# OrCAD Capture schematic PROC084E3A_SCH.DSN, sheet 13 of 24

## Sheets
13 09. PRG0 GB_ETHERNET RGMII 1: size C; title: PRG0 GB_ETHERNET RGMII 1
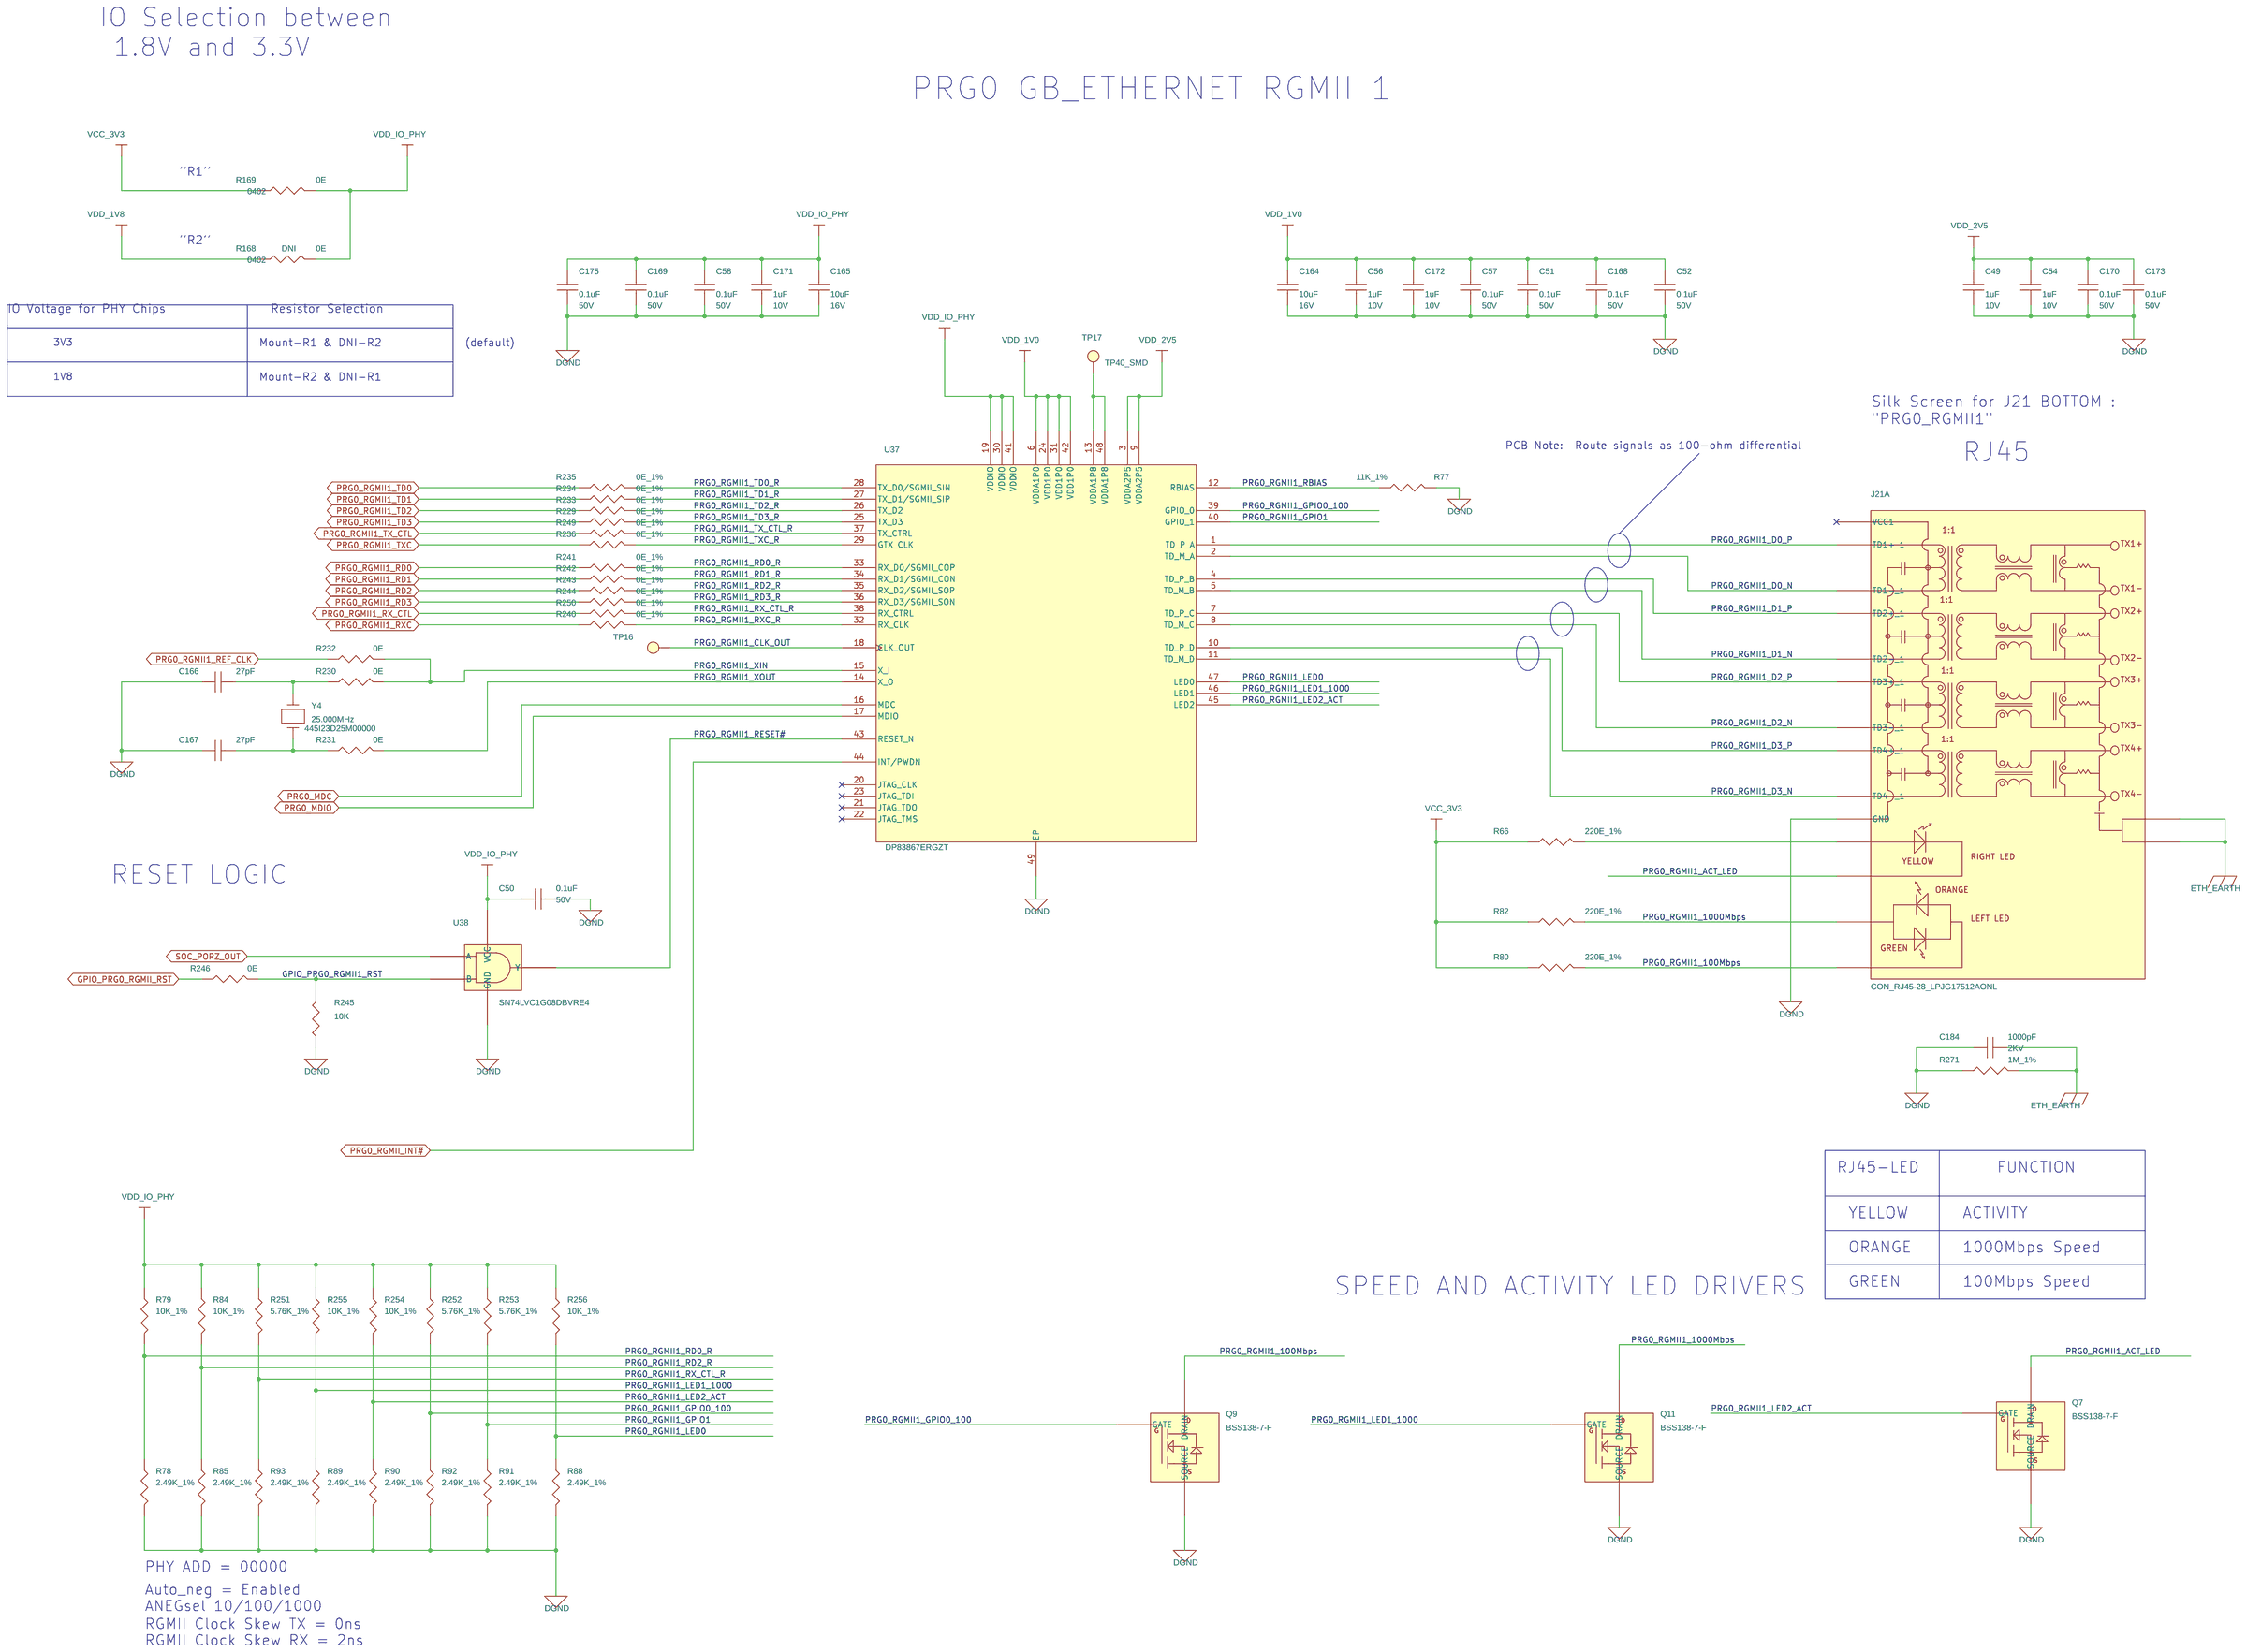
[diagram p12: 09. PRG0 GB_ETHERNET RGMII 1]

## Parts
C49  1uF  [CAP0402_0-75]
C50  0.1uF  [CAP0402_0-75]
C51  0.1uF  [CAP0402_0-75]
C52  0.1uF  [CAP0402_0-75]
C54  1uF  [CAP0402_0-75]
C56  1uF  [CAP0402_0-75]
C57  0.1uF  [CAP0402_0-75]
C58  0.1uF  [CAP0402_0-75]
C164  10uF  [CAP0805_1-5]
C165  10uF  [CAP0805_1-5]
C166  27pF  [CAP0402_0-75]
C167  27pF  [CAP0402_0-75]
C168  0.1uF  [CAP0402_0-75]
C169  0.1uF  [CAP0402_0-75]
C170  0.1uF  [CAP0402_0-75]
C171  1uF  [CAP0402_0-75]
C172  1uF  [CAP0402_0-75]
C173  0.1uF  [CAP0402_0-75]
C175  0.1uF  [CAP0402_0-75]
C184  1000pF  [CAP1206_1-75]
J21  CON_RJ45-28_LPJG17512AONL  [CON_RJ45-28_LPJG17512_S_R_T_25-3]  (sections A,B)
Q7  BSS138-7-F  [SOT23-123_1-1]
Q9  BSS138-7-F  [SOT23-123_1-1]
Q11  BSS138-7-F  [SOT23-123_1-1]
R66  220E_1%  [RES0402_0-5]
R77  11K_1%  [RES0402_0-5]
R78  2.49K_1%  [RES0402_0-5]
R79  10K_1%  [RES0402_0-5]
R80  220E_1%  [RES0402_0-5]
R82  220E_1%  [RES0402_0-5]
R84  10K_1%  [RES0402_0-5]
R85  2.49K_1%  [RES0402_0-5]
R88  2.49K_1%  [RES0402_0-5]
R89  2.49K_1%  [RES0402_0-5]
R90  2.49K_1%  [RES0402_0-5]
R91  2.49K_1%  [RES0402_0-5]
R92  2.49K_1%  [RES0402_0-5]
R93  2.49K_1%  [RES0402_0-5]
R168  0E  [RES0402_0-5]
R169  0E  [RES0402_0-5]
R229  0E_1%  [RES0402_0-5]
R230  0E  [RES0402_0-5]
R231  0E  [RES0402_0-5]
R232  0E  [RES0402_0-5]
R233  0E_1%  [RES0402_0-5]
R234  0E_1%  [RES0402_0-5]
R235  0E_1%  [RES0402_0-5]
R236  0E_1%  [RES0402_0-5]
R240  0E_1%  [RES0402_0-5]
R241  0E_1%  [RES0402_0-5]
R242  0E_1%  [RES0402_0-5]
R243  0E_1%  [RES0402_0-5]
R244  0E_1%  [RES0402_0-5]
R245  10K  [RES0402_0-5]
R246  0E  [RES0402_0-5]
R249  0E_1%  [RES0402_0-5]
R250  0E_1%  [RES0402_0-5]
R251  5.76K_1%  [RES0402_0-5]
R252  5.76K_1%  [RES0402_0-5]
R253  5.76K_1%  [RES0402_0-5]
R254  10K_1%  [RES0402_0-5]
R255  10K_1%  [RES0402_0-5]
R256  10K_1%  [RES0402_0-5]
R271  1M_1%  [RES0805_0-75]
TP16  TP40_SMD  [TP40_SMD]
TP17  TP40_SMD  [TP40_SMD]
U37  DP83867ERGZT  [VQFN48_19-68_285X285]
U38  SN74LVC1G08DBVRE4  [SOT23-5]
Y4  25.000MHz  [XTAL_ABM3_205X130_SMD_1-4]

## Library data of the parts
C49 C54 C56 C171 C172 = CAP: CAP CERAMIC 1uF 10V 10% X5R 0402; Chkd/date: MANIRAJA/020718; Crtd /date: SARANYA/060514; Custom_Duty: 15%; Customs_HS_Code: 85322990; Distributor_name: DIGIKEY; Distributor_part_number: 478-4596-1-ND; Footprint Path: Y:\MIS_DATABASE\Library\ALTIUM_TOOL\PCB_FOOTPRINTS\Altium_Footprint_Lib.PcbLib; Height: 0.56MM; Library Path: Y:\MIS_DATABASE\Library\ALTIUM_TOOL\SCHEMATICS_PARTS\MS_DISCRETE_Library.schlib; Mfr_name: AVX CORPORATION; Mfr_part_number: 0402ZD105KAT2A; Mistral Part No: 120014050010-R; Package: 0402; Part_type: CAPACITORS\CERAMIC; Project: AEGIS GP BETA2; RoHS: RoHS; Temperature: -55°C+85°C; Tolerance: 10%; Voltage: 10V; Wattage: NA; Weight: 0.65mg; Datasheet: Y:\MIS_DATABASE\DATASHEETS\CAPACITORS\AVX_MLC.PDF
C50-C52 C57 C58 C168-C170 C173 C175 = CAP: CAP CERAMIC 0.1uF 50V 10% X7R 0402; Chkd/date: VASANTHA/281216; Crtd /date: CHAITHANYA/051011; Custom_Duty: 15%; Customs_HS_Code: 85322990; Distributor_name: DIGIKEY; Distributor_part_number: 445-173610-1-ND; Footprint Path: Y:\MIS_DATABASE\Library\ALTIUM_TOOL\PCB_FOOTPRINTS\Altium_Footprint_Lib.PcbLib; Height: 0.60MM; Library Path: Y:\MIS_DATABASE\Library\ALTIUM_TOOL\SCHEMATICS_PARTS\MS_DISCRETE_Library.schlib; Mfr_name: TDK CORPORATION; Mfr_part_number: C1005X7R1H104K050BE; Mistral Part No: 120011100014-R; Package: 0402; Part_type: CAPACITORS\CERAMIC; Project: VP-4000-BASE-BOARD; RoHS: RoHS; Temperature: -55°C+125°C; Tolerance: 10%; Voltage: 50V; Wattage: NA; Weight: 0.65mg; Datasheet: Y:\MIS_DATABASE\DATASHEETS\CAPACITORS\TDK_C-SER_FEB19.PDF
C164 C165 = CAP: CAP CERAMIC 10uF 16V 10% X5R 0805; Chkd/date: SHREESHAIL/220506; Crtd /date: MAZHAR/150506; Custom_Duty: 15%; Customs_HS_Code: 85322990; Distributor_name: DIGIKEY; Distributor_part_number: 490-3886-1-ND; Footprint Path: Y:\MIS_DATABASE\Library\ALTIUM_TOOL\PCB_FOOTPRINTS\Altium_Footprint_Lib.PcbLib; Height: 1.35MM; Library Path: Y:\MIS_DATABASE\Library\ALTIUM_TOOL\SCHEMATICS_PARTS\MS_DISCRETE_Library.schlib; Mfr_name: MURATA; Mfr_part_number: GRM21BR61C106KE15L; Mistral Part No: 120009030205-R; Package: 0805; Part_type: CAPACITORS\CERAMIC; Project: VOCERA; RoHS: RoHS; Temperature: -55°C+85°C; Tolerance: 10%; Voltage: 16V; Wattage: NA; Weight: 9.5mg; Datasheet: Y:\MIS_DATABASE\DATASHEETS\CAPACITORS\MURATA-GXX-SER_NOV17.PDF
C166 = CAP: CAP CERAMIC 27pF 50V 5% C0G(NP0) 0402; Chkd/date: MAZHAR/241208; Crtd /date: GEETHA/090606; Custom_Duty: 15%; Customs_HS_Code: 85322990; Distributor_name: DIGIKEY; Distributor_part_number: 311-1019-1-ND; Footprint Path: Y:\MIS_DATABASE\Library\ALTIUM_TOOL\PCB_FOOTPRINTS\Altium_Footprint_Lib.PcbLib; Height: 0.55MM; Library Path: Y:\MIS_DATABASE\Library\ALTIUM_TOOL\SCHEMATICS_PARTS\MS_DISCRETE_Library.schlib; Mfr_name: YAGEO AMERICA; Mfr_part_number: CC0402JRNPO9BN270; Mistral Part No: 120014100024-R; Package: 0402; Part_type: CAPACITORS\CERAMIC; Project: PNAV; RoHS: RoHS; Temperature: -55°C+125°C; Tolerance: 5%; Voltage: 50V; Wattage: NA; Weight: 0.65mg; Datasheet: Y:\MIS_DATABASE\DATASHEETS\CAPACITORS\YACC-NPO.PDF
C167 = CAP: CAP CERAMIC 27pF 50V 5% C0G(NP0) 0402; Chkd/date: MAZHAR/241208; Crtd /date: GEETHA/090606; Custom_Duty: 15%; Customs_HS_Code: 85322990; Distributor_name: DIGIKEY; Distributor_part_number: 311-1019-1-ND; Footprint Path: Y:\MIS_DATABASE\Library\ALTIUM_TOOL\PCB_FOOTPRINTS\Altium_Footprint_Lib.PcbLib; Height: 0.55MM; Library Path: Y:\MIS_DATABASE\Library\ALTIUM_TOOL\SCHEMATICS_PARTS\MS_DISCRETE_Library.schlib; Mfr_name: YAGEO AMERICA; Mfr_part_number: CC0402JRNPO9BN270; Mistral Part No: 120014100024-R; Package: 0402; Part_type: CAPACITORS\CERAMIC; Project: PNAV; RoHS: RoHS; SIGNAL_MODEL: INS23888586; Temperature: -55°C+125°C; Tolerance: 5%; Voltage: 50V; Wattage: NA; Weight: 0.65mg; Datasheet: Y:\MIS_DATABASE\DATASHEETS\CAPACITORS\YACC-NPO.PDF
C184 = CAP: CAP CERAMIC 1000pF 2KV 10% X7R 1206; Chkd/date: SHREESHAIL/291106; Crtd /date: MAZHAR/281106; Custom_Duty: 15%; Customs_HS_Code: 85322990; Distributor_name: DIGIKEY; Distributor_part_number: 478-2956-1-ND; Footprint Path: Y:\MIS_DATABASE\Library\ALTIUM_TOOL\PCB_FOOTPRINTS\Altium_Footprint_Lib.PcbLib; Height: 1.52MM; Library Path: Y:\MIS_DATABASE\Library\ALTIUM_TOOL\SCHEMATICS_PARTS\MS_DISCRETE_Library.schlib; Mfr_name: AVX CORPORATION; Mfr_part_number: 1206GC102KAT1A; Mistral Part No: 120015080006-R; Package: 1206; Part_type: CAPACITORS\CERAMIC; Project: ADR1B; RoHS: RoHS; Temperature: -55°C+125°C; Tolerance: 10%; Voltage: 2KV; Wattage: NA; Weight: 16.2mg; Datasheet: Y:\MIS_DATABASE\DATASHEETS\CAPACITORS\AVX_HV-MLC.PDF
J21 = CON_RJ45-28_LPJG17512AONL: CON JACK RJ45 28POS REGISTERED FEMALE RA TH; Chkd/date: MANIRAJA/010817; Crtd /date: MANIRAJA/010817; Custom_Duty: 24%; Customs_HS_Code: 85369090; Distributor_name: NA; Distributor_part_number: NA; Height: 25.30MM; Mfr_name: LINK-PP; Mfr_part_number: LPJG17512AONL; Mistral Part No: 150017080001-R; Package: THRU-HOLE; Part_type: CONNECTOR\JACK; Project: TI_SVB_DUT; RoHS: RoHS; Temperature: 0°C+70°C; Tolerance: NA; Voltage: NA; Wattage: NA; Weight: NA; Datasheet: Y:\MIS_DATABASE\DATASHEETS\CONNECTORS\LPJG17512AONL.PDF
Q7 Q9 Q11 = MOSFET_2N7002_SOT23: IC MOSFET N-CHANNEL 50V 200mA SOT23-123; Chkd/date: MANIRAJA/190618; Crtd /date: USMAN/240709; Custom_Duty: 15%; Customs_HS_Code: 85423100; Distributor_name: DIGIKEY; Distributor_part_number: BSS138-FDICT-ND; Footprint Path: Y:\MIS_DATABASE\Library\ALTIUM_TOOL\PCB_FOOTPRINTS\Altium_Footprint_Lib.PcbLib; Height: 1.10MM; Library Path: Y:\MIS_DATABASE\Library\ALTIUM_TOOL\SCHEMATICS_PARTS\MS_MOSFET_Library.schlib; Mfr_name: DIODES INC; Mistral Part No: 142009070019-R; Package: SOT23-123; Part_type: ICS\POWER\MOSFET; Project: KHAN_MAIN; RoHS: RoHS; Temperature: -55°C+150°C; Tolerance: NA; Voltage: 50V; Wattage: 300mW; Weight: 8mg; Datasheet: Y:\MIS_DATABASE\DATASHEETS\DISCRETES\TRANSISTORS_FETS\BSS138.PDF
R66 R80 R82 = RESISTOR: RES 220E 1/10W 1% 0402; Chkd/date: MANIRAJA/130617; Crtd /date: BAVISH/260711; Custom_Duty: 15%; Customs_HS_Code: 85332119; Distributor_name: DIGIKEY; Distributor_part_number: P220LCT-ND; Footprint Path: Y:\MIS_DATABASE\Library\ALTIUM_TOOL\PCB_FOOTPRINTS\Altium_Footprint_Lib.PcbLib; Height: 0.40MM; Library Path: Y:\MIS_DATABASE\Library\ALTIUM_TOOL\SCHEMATICS_PARTS\MS_DISCRETE_Library.schlib; Mfr_name: PANASONIC-ECG; Mfr_part_number: ERJ-2RKF2200X; Mistral Part No: 110011070017-R; Package: 0402; Part_type: RESISTORS\FIXED; Project: LSM; RoHS: RoHS; Temperature: -55°C+155°C; Tolerance: 1%; Voltage: NA; Wattage: 1/10W; Weight: 0.8mg; Datasheet: Y:\MIS_DATABASE\DATASHEETS\RESISTORS\PAN-ERJSER_NOV17.PDF
R77 = RESISTOR: RES 11K 1/16W 1% 0402; Chkd/date: VASANTHA/251115; Crtd /date: VASANTHA/251115; Custom_Duty: 15%; Customs_HS_Code: 85332119; Distributor_name: DIGIKEY; Distributor_part_number: 311-11.0KLRCT-ND; Footprint Path: Y:\MIS_DATABASE\Library\ALTIUM_TOOL\PCB_FOOTPRINTS\Altium_Footprint_Lib.PcbLib; Height: 0.40MM; Library Path: Y:\MIS_DATABASE\Library\ALTIUM_TOOL\SCHEMATICS_PARTS\MS_DISCRETE_Library.schlib; Mfr_name: YAGEO AMERICA; Mfr_part_number: RC0402FR-0711KL; Mistral Part No: 110015110012-R; Package: 0402; Part_type: RESISTORS\FIXED; Project: TI_VLAN_SWITCH; RoHS: RoHS; Temperature: -55°C+155°C; Tolerance: 1%; Voltage: NA; Wattage: 1/16W; Weight: 0.65mg; Datasheet: Y:\MIS_DATABASE\DATASHEETS\RESISTORS\RCXXXXL-SER_MAR18.PDF
R78 R85 R88 R90-R92 = RESISTOR: RES 2.49K 1/16W 1% 0402; Assembly_Instruction: DNI; Chkd/date: VASANTHA/270516; Crtd /date: VASANTHA/270516; Custom_Duty: 15%; Customs_HS_Code: 85332119; Distributor_name: DIGIKEY; Distributor_part_number: 311-2.49KLRCT-ND; Footprint Path: Y:\MIS_DATABASE\Library\ALTIUM_TOOL\PCB_FOOTPRINTS\Altium_Footprint_Lib.PcbLib; Height: 0.40MM; Library Path: Y:\MIS_DATABASE\Library\ALTIUM_TOOL\SCHEMATICS_PARTS\MS_DISCRETE_Library.schlib; Mfr_name: YAGEO AMERICA; Mfr_part_number: RC0402FR-072K49L; Mistral Part No: 110016050020-R; Package: 0402; Part_type: RESISTORS\FIXED; Project: TMDXCSKCC; RoHS: RoHS; Temperature: -55°C+155°C; Tolerance: 1%; Voltage: NA; Wattage: 1/16W; Weight: 0.65mg; Datasheet: Y:\MIS_DATABASE\DATASHEETS\RESISTORS\RCXXXXL-SER_MAR18.PDF
R79 R84 R254 R256 = RESISTOR: RES 10K 1/16W 1% 0402; Assembly_Instruction: DNI; Chkd/date: VASANTHA/201216; Crtd /date: GEETHA/290506; Custom_Duty: 15%; Customs_HS_Code: 85332119; Distributor_name: DIGIKEY; Distributor_part_number: 311-10.0KLRTR-ND; Footprint Path: Y:\MIS_DATABASE\Library\ALTIUM_TOOL\PCB_FOOTPRINTS\Altium_Footprint_Lib.PcbLib; Height: 0.40MM; Library Path: Y:\MIS_DATABASE\Library\ALTIUM_TOOL\SCHEMATICS_PARTS\MS_DISCRETE_Library.schlib; Mfr_name: YAGEO AMERICA; Mfr_part_number: RC0402FR-0710KL; Mistral Part No: 110015090015-R; Package: 0402; Part_type: RESISTORS\FIXED; Project: VOCERA; RoHS: RoHS; Temperature: -55°C+155°C; Tolerance: 1%; Voltage: NA; Wattage: 1/16W; Weight: 0.65mg; Datasheet: Y:\MIS_DATABASE\DATASHEETS\RESISTORS\RCXXXXL-SER_MAR18.PDF
R89 R93 = RESISTOR: RES 2.49K 1/16W 1% 0402; Chkd/date: VASANTHA/270516; Crtd /date: VASANTHA/270516; Custom_Duty: 15%; Customs_HS_Code: 85332119; Distributor_name: DIGIKEY; Distributor_part_number: 311-2.49KLRCT-ND; Footprint Path: Y:\MIS_DATABASE\Library\ALTIUM_TOOL\PCB_FOOTPRINTS\Altium_Footprint_Lib.PcbLib; Height: 0.40MM; Library Path: Y:\MIS_DATABASE\Library\ALTIUM_TOOL\SCHEMATICS_PARTS\MS_DISCRETE_Library.schlib; Mfr_name: YAGEO AMERICA; Mfr_part_number: RC0402FR-072K49L; Mistral Part No: 110016050020-R; Package: 0402; Part_type: RESISTORS\FIXED; Project: TMDXCSKCC; RoHS: RoHS; Temperature: -55°C+155°C; Tolerance: 1%; Voltage: NA; Wattage: 1/16W; Weight: 0.65mg; Datasheet: Y:\MIS_DATABASE\DATASHEETS\RESISTORS\RCXXXXL-SER_MAR18.PDF
R168 = RESISTOR: RES 0E 1/10W JUMPER 0402; Assembly_Instruction: DNI; Chkd/date: VASANTHA/061216; Crtd /date: NAVEED/201014; Custom_Duty: 15%; Customs_HS_Code: 85332119; Distributor_name: DIGIKEY; Distributor_part_number: P0.0JCT-ND; Footprint Path: Y:\MIS_DATABASE\Library\ALTIUM_TOOL\PCB_FOOTPRINTS\Altium_Footprint_Lib.PcbLib; Height: 0.40MM; IBISSP_MODLES: VALUE REPEATING 2 TIME; Library Path: Y:\MIS_DATABASE\Library\ALTIUM_TOOL\SCHEMATICS_PARTS\MS_DISCRETE_Library.schlib; Mfr_name: PANASONIC-ECG; Mfr_part_number: ERJ-2GE0R00X; Mistral Part No: 110018030052-R; Package: 0402; Part_type: RESISTORS\FIXED; Project: AEGIS POM; RoHS: RoHS; SIGNAL_MODEL: INS23888567; Temperature: -55°C+155°C; Tolerance: NA; Voltage: NA; Wattage: 1/10W; Weight: 0.8mg; Datasheet: Y:\MIS_DATABASE\DATASHEETS\RESISTORS\PAN-ERJSER_NOV17.PDF
R169 = RESISTOR: RES 0E 1/10W JUMPER 0402; Chkd/date: VASANTHA/061216; Crtd /date: NAVEED/201014; Custom_Duty: 15%; Customs_HS_Code: 85332119; Distributor_name: DIGIKEY; Distributor_part_number: P0.0JCT-ND; Footprint Path: Y:\MIS_DATABASE\Library\ALTIUM_TOOL\PCB_FOOTPRINTS\Altium_Footprint_Lib.PcbLib; Height: 0.40MM; IBISSP_MODLES: VALUE REPEATING 2 TIME; Library Path: Y:\MIS_DATABASE\Library\ALTIUM_TOOL\SCHEMATICS_PARTS\MS_DISCRETE_Library.schlib; Mfr_name: PANASONIC-ECG; Mfr_part_number: ERJ-2GE0R00X; Mistral Part No: 110018030052-R; Package: 0402; Part_type: RESISTORS\FIXED; Project: AEGIS POM; RoHS: RoHS; SIGNAL_MODEL: INS23888567; Temperature: -55°C+155°C; Tolerance: NA; Voltage: NA; Wattage: 1/10W; Weight: 0.8mg; Datasheet: Y:\MIS_DATABASE\DATASHEETS\RESISTORS\PAN-ERJSER_NOV17.PDF
R229 R233-R236 R249 = RESISTOR: RES 0E 1/16W 1% 0402; Chkd/date: MAZHAR/220709; Crtd /date: USMAN/270109; Custom_Duty: 15%; Customs_HS_Code: 85332119; Distributor_name: DIGIKEY; Distributor_part_number: 311-0.0LRCT-ND; Footprint Path: Y:\MIS_DATABASE\Library\ALTIUM_TOOL\PCB_FOOTPRINTS\Altium_Footprint_Lib.PcbLib; Height: 0.40MM; Library Path: Y:\MIS_DATABASE\Library\ALTIUM_TOOL\SCHEMATICS_PARTS\MS_DISCRETE_Library.schlib; Mfr_name: YAGEO AMERICA; Mfr_part_number: RC0402FR-070RL; Mistral Part No: 110009030085-R; Package: 0402; Part_type: RESISTORS\FIXED; Project: OMAP_EVM; RoHS: RoHS; SIGNAL_MODEL: INS23888567; Temperature: -55°C+155°C; Tolerance: 1%; Voltage: NA; Wattage: 1/16W; Weight: 0.65mg; Datasheet: Y:\MIS_DATABASE\DATASHEETS\RESISTORS\RCXXXXL-SER_MAR18.PDF
R230 R231 R246 = RESISTOR: RES 0E 1/10W JUMPER 0402; Chkd/date: MANIRAJA/290318; Crtd /date: ALVY/270318; Custom_Duty: 15%; Customs_HS_Code: 85332119; Distributor_name: DIGIKEY; Distributor_part_number: MCS0402-0.0-ZZCT-ND; Footprint Path: Y:\MIS_DATABASE\Library\ALTIUM_TOOL\PCB_FOOTPRINTS\Altium_Footprint_Lib.PcbLib; Height: 0.37MM; Library Path: Y:\MIS_DATABASE\Library\ALTIUM_TOOL\SCHEMATICS_PARTS\MS_DISCRETE_Library.schlib; Mfr_name: VISHAY; Mfr_part_number: MCS04020Z0000ZE000; Mistral Part No: 110018030052-R; Package: 0402; Part_type: RESISTORS\FIXED; Project: DRDL_ITS2-SC; RoHS: RoHS; SIGNAL_MODEL: INS23888567; Temperature: -55°C+155°C; Tolerance: NA; Voltage: NA; Wattage: 1/10W; Weight: 0.65mg; Datasheet: Y:\MIS_DATABASE\DATASHEETS\RESISTORS\MCTXXXXC-SER.PDF
R232 = RESISTOR: RES 0E 1/10W JUMPER 0402; Assembly_Instruction: DNI; Chkd/date: MANIRAJA/290318; Crtd /date: ALVY/270318; Custom_Duty: 15%; Customs_HS_Code: 85332119; Distributor_name: DIGIKEY; Distributor_part_number: MCS0402-0.0-ZZCT-ND; Footprint Path: Y:\MIS_DATABASE\Library\ALTIUM_TOOL\PCB_FOOTPRINTS\Altium_Footprint_Lib.PcbLib; Height: 0.37MM; Library Path: Y:\MIS_DATABASE\Library\ALTIUM_TOOL\SCHEMATICS_PARTS\MS_DISCRETE_Library.schlib; Mfr_name: VISHAY; Mfr_part_number: MCS04020Z0000ZE000; Mistral Part No: 110018030052-R; Package: 0402; Part_type: RESISTORS\FIXED; Project: DRDL_ITS2-SC; RoHS: RoHS; SIGNAL_MODEL: INS23888567; Temperature: -55°C+155°C; Tolerance: NA; Voltage: NA; Wattage: 1/10W; Weight: 0.65mg; Datasheet: Y:\MIS_DATABASE\DATASHEETS\RESISTORS\MCTXXXXC-SER.PDF
R240-R244 R250 = RESISTOR: RES 0E 1/16W 1% 0402; Chkd/date: MAZHAR/220709; Crtd /date: USMAN/270109; Custom_Duty: 15%; Customs_HS_Code: 85332119; Distributor_name: DIGIKEY; Distributor_part_number: 311-0.0LRCT-ND; Footprint Path: Y:\MIS_DATABASE\Library\ALTIUM_TOOL\PCB_FOOTPRINTS\Altium_Footprint_Lib.PcbLib; Height: 0.40MM; Library Path: Y:\MIS_DATABASE\Library\ALTIUM_TOOL\SCHEMATICS_PARTS\MS_DISCRETE_Library.schlib; Mfr_name: YAGEO AMERICA; Mfr_part_number: RC0402FR-070RL; Mistral Part No: 110009030085-R; Package: 0402; Part_type: RESISTORS\FIXED; Project: OMAP_EVM; RoHS: RoHS; SIGNAL_MODEL: RESISTOR_RES0402_22E_1%_22E_1%; Temperature: -55°C+155°C; Tolerance: 1%; Voltage: NA; Wattage: 1/16W; Weight: 0.65mg; Datasheet: Y:\MIS_DATABASE\DATASHEETS\RESISTORS\RCXXXXL-SER_MAR18.PDF
R245 = RESISTOR: RES 10K 1/16W 5% 0402; Chkd/date: VASANTHA/061216; Crtd /date: MAZHAR/230805; Custom_Duty: 15%; Customs_HS_Code: 85332119; Distributor_name: DIGIKEY; Distributor_part_number: 311-10KJRCT-ND; Footprint Path: Y:\MIS_DATABASE\Library\ALTIUM_TOOL\PCB_FOOTPRINTS\Altium_Footprint_Lib.PcbLib; Height: 0.40MM; Library Path: Y:\MIS_DATABASE\Library\ALTIUM_TOOL\SCHEMATICS_PARTS\MS_DISCRETE_Library.schlib; Loading: DNI; Mfr_name: YAGEO AMERICA; Mfr_part_number: RC0402JR-0710KL; Mistral Part No: 110011060021-R; Package: 0402; Part_type: RESISTORS\FIXED; Project: HSE; RoHS: RoHS; Temperature: -55°C+155°C; Tolerance: 5%; Voltage: NA; Wattage: 1/16W; Weight: 0.65mg; Datasheet: Y:\MIS_DATABASE\DATASHEETS\RESISTORS\RCXXXXL-SER_MAR18.PDF
R251 = RESISTOR: RES 5.76K 1/10W 1% 0402; Chkd/date: MAZHAR/150709; Crtd /date: USMAN/220808; Custom_Duty: 15%; Customs_HS_Code: 85332119; Distributor_name: DIGIKEY; Distributor_part_number: P5.76KLCT-ND; Footprint Path: Y:\MIS_DATABASE\Library\ALTIUM_TOOL\PCB_FOOTPRINTS\Altium_Footprint_Lib.PcbLib; Height: 0.40MM; Library Path: Y:\MIS_DATABASE\Library\ALTIUM_TOOL\SCHEMATICS_PARTS\MS_DISCRETE_Library.schlib; Mfr_name: PANASONIC-ECG; Mfr_part_number: ERJ-2RKF5761X; Mistral Part No: 110009030945-R; Package: 0402; Part_type: RESISTORS\FIXED; Project: CPB; RoHS: RoHS; Temperature: -55°C+155°C; Tolerance: 1%; Voltage: NA; Wattage: 1/10W; Weight: 0.8mg; Datasheet: Y:\MIS_DATABASE\DATASHEETS\RESISTORS\PAN-ERJSER_NOV17.PDF
R252 R253 = RESISTOR: RES 5.76K 1/10W 1% 0402; Assembly_Instruction: DNI; Chkd/date: MAZHAR/150709; Crtd /date: USMAN/220808; Custom_Duty: 15%; Customs_HS_Code: 85332119; Distributor_name: DIGIKEY; Distributor_part_number: P5.76KLCT-ND; Footprint Path: Y:\MIS_DATABASE\Library\ALTIUM_TOOL\PCB_FOOTPRINTS\Altium_Footprint_Lib.PcbLib; Height: 0.40MM; Library Path: Y:\MIS_DATABASE\Library\ALTIUM_TOOL\SCHEMATICS_PARTS\MS_DISCRETE_Library.schlib; Mfr_name: PANASONIC-ECG; Mfr_part_number: ERJ-2RKF5761X; Mistral Part No: 110009030945-R; Package: 0402; Part_type: RESISTORS\FIXED; Project: CPB; RoHS: RoHS; Temperature: -55°C+155°C; Tolerance: 1%; Voltage: NA; Wattage: 1/10W; Weight: 0.8mg; Datasheet: Y:\MIS_DATABASE\DATASHEETS\RESISTORS\PAN-ERJSER_NOV17.PDF
R255 = RESISTOR: RES 10K 1/16W 1% 0402; Chkd/date: VASANTHA/201216; Crtd /date: GEETHA/290506; Custom_Duty: 15%; Customs_HS_Code: 85332119; Distributor_name: DIGIKEY; Distributor_part_number: 311-10.0KLRTR-ND; Footprint Path: Y:\MIS_DATABASE\Library\ALTIUM_TOOL\PCB_FOOTPRINTS\Altium_Footprint_Lib.PcbLib; Height: 0.40MM; Library Path: Y:\MIS_DATABASE\Library\ALTIUM_TOOL\SCHEMATICS_PARTS\MS_DISCRETE_Library.schlib; Mfr_name: YAGEO AMERICA; Mfr_part_number: RC0402FR-0710KL; Mistral Part No: 110015090015-R; Package: 0402; Part_type: RESISTORS\FIXED; Project: VOCERA; RoHS: RoHS; Temperature: -55°C+155°C; Tolerance: 1%; Voltage: NA; Wattage: 1/16W; Weight: 0.65mg; Datasheet: Y:\MIS_DATABASE\DATASHEETS\RESISTORS\RCXXXXL-SER_MAR18.PDF
R271 = RESISTOR: RES 1M 1/8W 1% 0805; Chkd/date: VASANTHA/150514; Crtd /date: BALACHANDAR/150514; Custom_Duty: 15%; Customs_HS_Code: 85332119; Distributor_name: DIGIKEY; Distributor_part_number: P1.00MCCT-ND; Footprint Path: Y:\MIS_DATABASE\Library\ALTIUM_TOOL\PCB_FOOTPRINTS\Altium_Footprint_Lib.PcbLib; Height: 0.70MM; Library Path: Y:\MIS_DATABASE\Library\ALTIUM_TOOL\SCHEMATICS_PARTS\MS_DISCRETE_Library.schlib; Mfr_name: PANASONIC-ECG; Mfr_part_number: ERJ-6ENF1004V; Mistral Part No: 110014100002-R; Package: 0805; Part_type: RESISTORS\FIXED; Project: HUMANWARE_PHOENIX; RoHS: RoHS; Temperature: -55°C+155°C; Tolerance: 1%; Voltage: NA; Wattage: 1/8W; Weight: 4mg; Datasheet: Y:\MIS_DATABASE\DATASHEETS\RESISTORS\PAN-ERJSER_NOV17.PDF
TP16 TP17 = TESTPOINT: TESTPOINT CIR 40 SMD; Chkd/date: MAZHAR/190505; Crtd /date: MAZHAR/190505; Distributor_name: NA; Distributor_part_number: NA; Footprint Path: Y:\MIS_DATABASE\Library\ALTIUM_TOOL\PCB_FOOTPRINTS\Altium_Footprint_Lib.PcbLib; Height: NA; Library Path: Y:\MIS_DATABASE\Library\ALTIUM_TOOL\SCHEMATICS_PARTS\MS_DISCRETE_Library.schlib; MECHANICAL 3D STEP FILE: NA; Mfr_name: LOCAL; Mistral Part No: 130009030933; Package: SMD; Project: RAINIER-3; RoHS: NA; Temperature: NA; Tolerance: NA; Voltage: NA; Wattage: NA; Weight: NA; Datasheet: NA
U37 = DP83867ERGZT_VQFN48: IC SMALL FORM FACTOR 10/100/1000 Mb/s ETHERNET PHY LAYER TRANSCEIVER VQFN48; Chkd/date: VASANTHA/251115; Crtd /date: VASANTHA/251115; Custom_Duty: 15%; Customs_HS_Code: 85423100; Distributor_name: DIGIKEY; Distributor_part_number: 296-43254-1-ND; Height: 1.00MM; Mfr_name: TEXAS INSTRUMENTS; Mistral Part No: 143015110004-R; Package: VQFN48; Part_type: ICS\TELECOM\TRANSCEIVER; Project: TI_VLAN_SWITCH; RoHS: RoHS; Temperature: -40°C+105°C; Tolerance: NA; Voltage: NA; Wattage: NA; Weight: NA; Datasheet: Y:\MIS_DATABASE\DATASHEETS\ICS\DIGITAL\BUSTRANSCEIVER\DP83867.PDF
U38 = SN74LVC1G08DBVRE4_SOT23-5: IC SINGLE 2-INPUT POSITIVE AND GATE SOT23-5; Chkd/date: SUHAS/221010; Crtd /date: USMAN/151008; Custom_Duty: 15%; Customs_HS_Code: 85423100; Distributor_name: DIGIKEY; Distributor_part_number: SN74LVC1G08DBVRE4-ND; Height: 1.45MM; Mfr_name: TEXAS INSTRUMENTS; Mistral Part No: 141009060026-R; Part_type: ICS\DIGITAL\GATES; Project: KHAN_MAIN; RoHS: Sb/ Br FREE; Temperature: -40°C+85°C; Datasheet: Y:\MIS_DATABASE\DATASHEETS\ICS\DIGITAL\GATES\SN74LVC1G08.PDF
Y4 = CRY: CRY 25.000MHz 18pF SMD; Chkd/date: VASANTHA/110316; Crtd /date: JEBRAN/090216; Custom_Duty: 24%; Customs_HS_Code: 85439000; Distributor_name: DIGIKEY; Distributor_part_number: CTX1175CT-ND; Footprint Path: Y:\MIS_DATABASE\Library\ALTIUM_TOOL\PCB_FOOTPRINTS\Altium_Footprint_Lib.PcbLib; Height: 1.35MM; Library Path: Y:\MIS_DATABASE\Library\ALTIUM_TOOL\SCHEMATICS_PARTS\MS_DISCRETE_Library.schlib; Mfr_name: CTS; Mfr_part_number: 445I23D25M00000; Mistral Part No: 130016020016-R; Package: SMD; Part_type: CRYSTAL; Project: PDI_MINIPCB; RoHS: RoHS; Temperature: -40°C+85°C; Tolerance: NA; Voltage: NA; Wattage: NA; Weight: 50mg; Datasheet: Y:\MIS_DATABASE\DATASHEETS\MISC\CRY_OSC\445.PDF

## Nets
DGND: C49.2 C50.2 C51.2 C52.2 C54.2 C56.2 C57.2 C58.2 C164.2 C165.2 C166.1 C167.1 C168.2 C169.2 C170.2 C171.2 C172.2 C173.2 C175.2 C184.1 J21.A10(GND) Q7.2(SOURCE) Q9.2(SOURCE) Q11.2(SOURCE) R77.1 R78.2 R85.2 R88.2 R89.2 R90.2 R91.2 R92.2 R93.2 R245.1 R271.1 U37.49(EP) U38.3(GND) ; also on sheet 1 2 3 8 9 10 11 12 14 15 16 17 18 19 20 21 22 23 24
VCC_3V3: R66.1 R80.1 R82.1 R169.2 ; also on sheet 1 2 3 8 9 10 11 12 14 15 16 17 18 19 20 22 23 24
VDD_1V0: C51.1 C52.1 C56.1 C57.1 C164.1 C168.1 C172.1 U37.6(VDDA1P0) U37.24(VDD1P0) U37.31(VDD1P0) U37.42(VDD1P0) ; also on sheet 14 15 16 23
VDD_1V8: R168.2 ; also on sheet 9 23
VDD_2V5: C49.1 C54.1 C170.1 C173.1 U37.3(VDDA2P5) U37.9(VDDA2P5) ; also on sheet 14 15 16 23
VDD_IO_PHY: C50.1 C58.1 C165.1 C169.1 C171.1 C175.1 R79.1 R84.1 R168.1 R169.1 R251.1 R252.1 R253.1 R254.1 R255.1 R256.1 U37.19(VDDIO) U37.30(VDDIO) U37.41(VDDIO) U38.5(VCC) ; also on sheet 12 14 15 16
ETH_EARTH: C184.2 J21.SH1 J21.SH2 R271.2 ; also on sheet 14 15 16 22
GPIO_PRG0_RGMII1_RST: R245.2 R246.2 U38.2(B)
GPIO_PRG0_RGMII_RST: R246.1 ; also on sheet 8 14
PRG0_MDC: U37.16(MDC) ; also on sheet 12 14
PRG0_MDIO: U37.17(MDIO) ; also on sheet 12 14
PRG0_RGMII1_100Mbps: J21.A13 Q9.3(DRAIN) R80.2
PRG0_RGMII1_1000Mbps: J21.A14 Q11.3(DRAIN) R82.2
PRG0_RGMII1_ACT_LED: J21.A11 Q7.3(DRAIN)
PRG0_RGMII1_CLK_OUT: TP16.1(TP) U37.18(CLK_OUT)
PRG0_RGMII1_D0_N: J21.A2(TD1-_1) U37.2(TD_M_A)
PRG0_RGMII1_D0_P: J21.A1(TD1+_1) U37.1(TD_P_A)
PRG0_RGMII1_D1_N: J21.A4(TD2-_1) U37.5(TD_M_B)
PRG0_RGMII1_D1_P: J21.A3(TD2+_1) U37.4(TD_P_B)
PRG0_RGMII1_D2_N: J21.A6(TD3-_1) U37.8(TD_M_C)
PRG0_RGMII1_D2_P: J21.A5(TD3+_1) U37.7(TD_P_C)
PRG0_RGMII1_D3_N: J21.A8(TD4-_1) U37.11(TD_M_D)
PRG0_RGMII1_D3_P: J21.A7(TD4+_1) U37.10(TD_P_D)
PRG0_RGMII1_GPIO0_100: Q9.1(GATE) R92.1 R252.2 U37.39(GPIO_0)
PRG0_RGMII1_GPIO1: R91.1 R253.2 U37.40(GPIO_1)
PRG0_RGMII1_LED0: R88.1 R256.2 U37.47(LED0)
PRG0_RGMII1_LED1_1000: Q11.1(GATE) R89.1 R255.2 U37.46(LED1)
PRG0_RGMII1_LED2_ACT: Q7.1(GATE) R90.1 R254.2 U37.45(LED2)
PRG0_RGMII1_RBIAS: R77.2 U37.12(RBIAS)
PRG0_RGMII1_RD0: R241.1 ; also on sheet 8
PRG0_RGMII1_RD0_R: R78.1 R79.2 R241.2 U37.33(RX_D0/SGMII_COP)
PRG0_RGMII1_RD1: R242.1 ; also on sheet 8
PRG0_RGMII1_RD1_R: R242.2 U37.34(RX_D1/SGMII_CON)
PRG0_RGMII1_RD2: R243.1 ; also on sheet 8
PRG0_RGMII1_RD2_R: R84.2 R85.1 R243.2 U37.35(RX_D2/SGMII_SOP)
PRG0_RGMII1_RD3: R244.1 ; also on sheet 8
PRG0_RGMII1_RD3_R: R244.2 U37.36(RX_D3/SGMII_SON)
PRG0_RGMII1_REF_CLK: R232.1 ; also on sheet 9
PRG0_RGMII1_RESET#: U37.43(RESET_N) U38.4(Y)
PRG0_RGMII1_RX_CTL: R250.1 ; also on sheet 8
PRG0_RGMII1_RX_CTL_R: R93.1 R250.2 R251.2 U37.38(RX_CTRL)
PRG0_RGMII1_RXC: R240.1 ; also on sheet 8
PRG0_RGMII1_RXC_R: R240.2 U37.32(RX_CLK)
PRG0_RGMII1_TD0: R235.1 ; also on sheet 8
PRG0_RGMII1_TD0_R: R235.2 U37.28(TX_D0/SGMII_SIN)
PRG0_RGMII1_TD1: R234.1 ; also on sheet 8
PRG0_RGMII1_TD1_R: R234.2 U37.27(TX_D1/SGMII_SIP)
PRG0_RGMII1_TD2: R233.1 ; also on sheet 8
PRG0_RGMII1_TD2_R: R233.2 U37.26(TX_D2)
PRG0_RGMII1_TD3: R229.1 ; also on sheet 8
PRG0_RGMII1_TD3_R: R229.2 U37.25(TX_D3)
PRG0_RGMII1_TX_CTL: R249.1 ; also on sheet 8
PRG0_RGMII1_TX_CTL_R: R249.2 U37.37(TX_CTRL)
PRG0_RGMII1_TXC: R236.1 ; also on sheet 8
PRG0_RGMII1_TXC_R: R236.2 U37.29(GTX_CLK)
PRG0_RGMII1_XIN: R230.2 R232.2 U37.15(X_I)
PRG0_RGMII1_XOUT: R231.2 U37.14(X_O)
PRG0_RGMII_INT#: U37.44(INT/PWDN) ; also on sheet 8 14
SOC_PORZ_OUT: U38.1(A) ; also on sheet 8 14 15 16 22
N22955114: C166.2 R230.1 Y4.2
N22955116: C167.2 R231.1 Y4.1
N23022026: TP17.1(TP) U37.13(VDDA1P8) U37.48(VDDA1P8)
N23027132: J21.A12 R66.2

Not connected (* = marked no-connect by the designer): J21 A9(VCC1)*; U37 20(JTAG_CLK)* 21(JTAG_TDO)* 22(JTAG_TMS)* 23(JTAG_TDI)*

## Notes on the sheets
sheet 13
- IO Selection between
   1.8V and 3.3V
- PRG0 GB_ETHERNET RGMII 1
- ''R1''
- ''R2''
- IO Voltage for PHY Chips
- Resistor Selection
- 3V3
- Mount-R1 & DNI-R2
- (default)
- 1V8
- Mount-R2 & DNI-R1
- Silk Screen for J21 BOTTOM :
  "PRG0_RGMII1"
- PCB Note:  Route signals as 100-ohm differential
- RJ45
- RESET LOGIC
- RJ45-LED
- FUNCTION
- YELLOW
- ACTIVITY
- ORANGE
- 1000Mbps Speed
- SPEED AND ACTIVITY LED DRIVERS
- GREEN
- 100Mbps Speed
- PHY ADD = 00000
- Auto_neg = Enabled
  ANEGsel 10/100/1000
- RGMII Clock Skew TX = 0ns
  RGMII Clock Skew RX = 2ns
